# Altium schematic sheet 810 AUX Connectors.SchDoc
size Letter; Organization: Toradex Solutions Inc.; Address1: 6415 Northwest Drive; Address2: Mississauga, ON, L4V 1X1; Address3: Canada
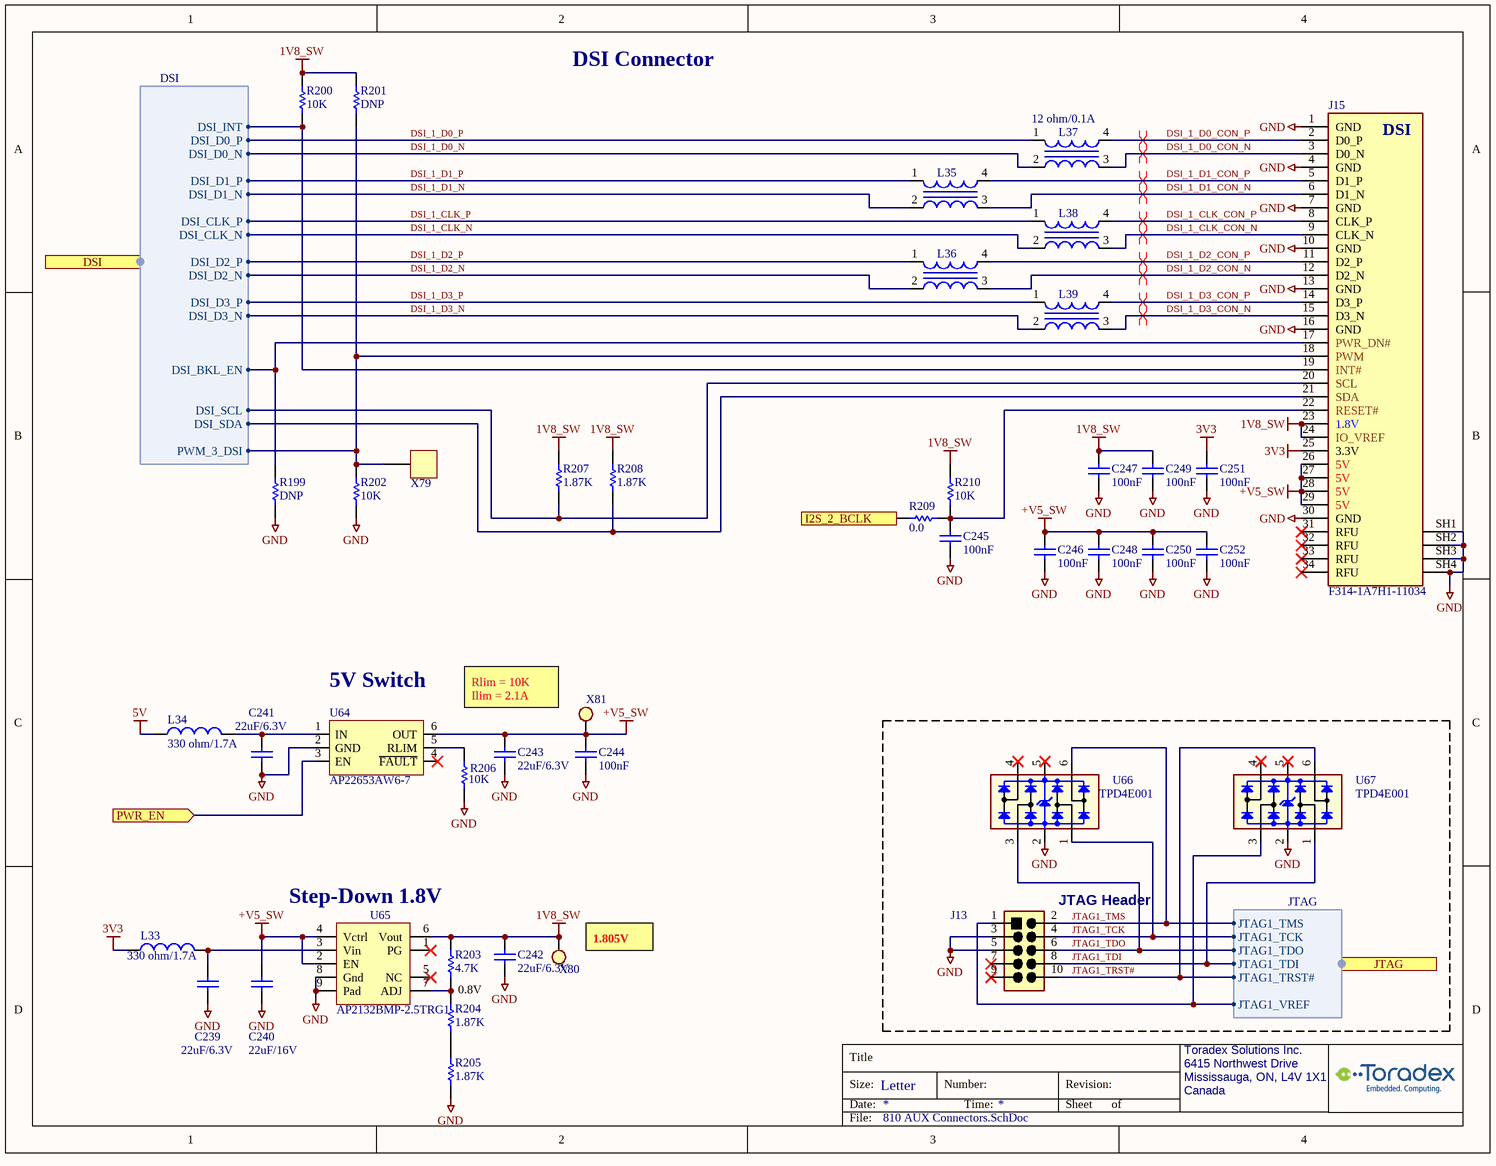
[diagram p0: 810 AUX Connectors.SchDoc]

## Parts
C239  22uF/6.3V  [C0402_CAPC1005L]
C240  value 22uF/16V  [C/0805]  (hidden comment: 1314-Cap-0805-22uF/16V)
C241  22uF/6.3V  [C0402_CAPC1005L]
C242  22uF/6.3V  [C0402_CAPC1005L]
C243  22uF/6.3V  [C0402_CAPC1005L]
C244  100nF  [C0402_CAPC1005L]
C245  100nF  [C0402_CAPC1005L]
C246  100nF  [C0402_CAPC1005L]
C247  100nF  [C0402_CAPC1005L]
C248  100nF  [C0402_CAPC1005L]
C249  100nF  [C0402_CAPC1005L]
C250  100nF  [C0402_CAPC1005L]
C251  100nF  [C0402_CAPC1005L]
C252  100nF  [C0402_CAPC1005L]
J13  FTSH-105-01-L-DV-K  [SAMTEC_FTSH-105-01-L-DV-K-TR]  (value not drawn)
J15  F314-1A7H1-11034  [AMPHENOL_F314-1A7H1-11034]
L33  value 330 ohm/1.7A  [INDC1608x095]  (hidden comment: 0405-Fer-0603-330ohm/1.7A)
L34  value 330 ohm/1.7A  [INDC1608x095]  (hidden comment: 0405-Fer-0603-330ohm/1.7A)
L35  12 ohm/0.1A  [COIL0302]  (value not drawn)
L36  12 ohm/0.1A  [COIL0302]  (value not drawn)
L37  12 ohm/0.1A  [COIL0302]
L38  12 ohm/0.1A  [COIL0302]  (value not drawn)
L39  12 ohm/0.1A  [COIL0302]  (value not drawn)
R199  value DNP  [R0402_RESC1005L]  (hidden comment: 0000-Res-0402-DNP)
R200  value 10K  [R0402_RESC1005L]  (hidden comment: 1572-Res-0402-10K)
R201  value DNP  [R0402_RESC1005L]  (hidden comment: 0000-Res-0402-DNP)
R202  value 10K  [R0402_RESC1005L]  (hidden comment: 1572-Res-0402-10K)
R203  value 4.7K  [R0402_RESC1005L]  (hidden comment: 2233-Res-0402-4.7K)
R204  value 1.87K  [R0402_RESC1005L]  (hidden comment: 1536-Res-0402-1.87K)
R205  value 1.87K  [R0402_RESC1005L]  (hidden comment: 1536-Res-0402-1.87K)
R206  value 10K  [R0402_RESC1005L]  (hidden comment: 1572-Res-0402-10K)
R207  value 1.87K  [R0402_RESC1005L]  (hidden comment: 1536-Res-0402-1.87K)
R208  value 1.87K  [R0402_RESC1005L]  (hidden comment: 1536-Res-0402-1.87K)
R209  value 0.0  [R/0603]  (hidden comment: 0195-Res-0603-0.0ohm)
R210  value 10K  [R0402_RESC1005L]  (hidden comment: 1572-Res-0402-10K)
U64  AP22653AW6-7  [sot23-6]
U65  AP2132BMP-2.5TRG1  [SOP-9 TP_ALT]
U66  TPD4E001  [SOT23-6]
U67  TPD4E001  [SOT23-6]
X79  000-TestPoint  [TestPoint_1]  (value not drawn)
X80  000-TestPoint2  [TestPoint_3]  (value not drawn)
X81  000-TestPoint2  [TestPoint_3]  (value not drawn)

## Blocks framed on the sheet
JTAG Header: J13 U66 U67

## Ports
DSI (harness DSI), I2S_2_BCLK (in), JTAG (harness JTAG), PWR_EN (in)

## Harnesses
JTAG: JTAG1_TDI, JTAG1_TRST#, JTAG1_TDO, JTAG1_VREF, JTAG1_TCK, JTAG1_TMS
DSI: DSI_SDA, DSI_SCL, DSI_BKL_EN, PWM_3_DSI, DSI_INT, DSI_D3_N, DSI_D3_P, DSI_D2_N, DSI_D2_P, DSI_CLK_N, DSI_CLK_P, DSI_D1_N, DSI_D1_P, DSI_D0_N, DSI_D0_P

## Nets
1V8_SW: C242.2 C247.2 C249.2 J15.23(1.8V) J15.24(IO_VREF) R200.2 R201.2 R203.2 R207.2 R208.2 R210.2 U65.6(Vout) X80.1
3V3: C251.2 J15.25(3.3V) L33.1
5V: L34.1
+V5_SW: C240.2 C243.2 C244.2 C246.2 C248.2 C250.2 C252.2 J15.26(5V) J15.27(5V) J15.28(5V) J15.29(5V) U64.6(OUT) U65.2(EN) U65.4(Vctrl) X81.1
GND: C239.1 C240.1 C241.1 C242.1 C243.1 C244.1 C245.1 C246.1 C247.1 C248.1 C249.1 C250.1 C251.1 C252.1 J13.3 J13.5 J15.1(GND) J15.4(GND) J15.7(GND) J15.10(GND) J15.13(GND) J15.16(GND) J15.30(GND) J15.SH1 J15.SH2 J15.SH3 J15.SH4 R199.1 R202.1 R205.1 R206.1 U64.2(GND) U65.8(Gnd) U65.9(Pad) U66.2 U67.2
DSI_1_CLK_CON_N: J15.9(CLK_N) L38.3
DSI_1_CLK_CON_P: J15.8(CLK_P) L38.4
DSI_1_CLK_N: L38.2 ; port DSI.DSI_CLK_N
DSI_1_CLK_P: L38.1 ; port DSI.DSI_CLK_P
DSI_1_D0_CON_N: J15.3(D0_N) L37.3
DSI_1_D0_CON_P: J15.2(D0_P) L37.4
DSI_1_D0_N: L37.2 ; port DSI.DSI_D0_N
DSI_1_D0_P: L37.1 ; port DSI.DSI_D0_P
DSI_1_D1_CON_N: J15.6(D1_N) L35.3
DSI_1_D1_CON_P: J15.5(D1_P) L35.4
DSI_1_D1_N: L35.2 ; port DSI.DSI_D1_N
DSI_1_D1_P: L35.1 ; port DSI.DSI_D1_P
DSI_1_D2_CON_N: J15.12(D2_N) L36.3
DSI_1_D2_CON_P: J15.11(D2_P) L36.4
DSI_1_D2_N: L36.2 ; port DSI.DSI_D2_N
DSI_1_D2_P: L36.1 ; port DSI.DSI_D2_P
DSI_1_D3_CON_N: J15.15(D3_N) L39.3
DSI_1_D3_CON_P: J15.14(D3_P) L39.4
DSI_1_D3_N: L39.2 ; port DSI.DSI_D3_N
DSI_1_D3_P: L39.1 ; port DSI.DSI_D3_P
I2S_2_BCLK: R209.1 ; port I2S_2_BCLK
JTAG1_TCK: J13.4 U66.1 ; port JTAG.JTAG1_TCK
JTAG1_TDI: J13.8 U67.1 ; port JTAG.JTAG1_TDI
JTAG1_TDO: J13.6 U66.3 ; port JTAG.JTAG1_TDO
JTAG1_TMS: J13.2 U66.6 ; port JTAG.JTAG1_TMS
JTAG1_TRST#: J13.10 U67.6 ; port JTAG.JTAG1_TRST#
PWR_EN: U64.3(EN) ; port PWR_EN
NetC239_2: C239.2 L33.2 U65.3(Vin)
NetC241_2: C241.2 L34.2 U64.1(IN)
NetC245_2: C245.2 J15.22(RESET#) R209.2 R210.1
NetJ13_1: J13.1 U67.3 ; port JTAG.JTAG1_VREF
NetJ15_17: J15.17(PWR_DN#) R199.2 ; port DSI.DSI_BKL_EN
NetJ15_18: J15.18(PWM) R201.1 R202.2 X79.1 ; port DSI.PWM_3_DSI
NetJ15_19: J15.19(INT#) R200.1 ; port DSI.DSI_INT
NetJ15_20: J15.20(SCL) R207.1 ; port DSI.DSI_SCL
NetJ15_21: J15.21(SDA) R208.1 ; port DSI.DSI_SDA
NetR203_1: R203.1 R204.2 U65.7(ADJ)
NetR204_1: R204.1 R205.2
NetR206_2: R206.2 U64.5(RLIM)

Not connected (* = marked no-connect by the designer): J13 7* 9*; J15 31(RFU)* 32(RFU)* 33(RFU)* 34(RFU)*; U64 4(~{FAULT})*; U65 1(PG)* 5(NC)*; U66 4* 5*; U67 4* 5*

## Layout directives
differential pair; differential pair class DSI; differential pair class DSI_1_CON: DSI_1_CLK_CON_N, DSI_1_CLK_CON_P, DSI_1_D0_CON_N, DSI_1_D0_CON_P, DSI_1_D1_CON_N, DSI_1_D1_CON_P, DSI_1_D2_CON_N, DSI_1_D2_CON_P, DSI_1_D3_CON_N, DSI_1_D3_CON_P

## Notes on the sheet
- DSI Connector
- (near U64) 5V Switch
- Rlim = 10K
  Ilim = 2.1A
- Step-Down 1.8V
- (near X80) 1.805V
- 0.8V

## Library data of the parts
C239 C241-C243 = 2404-Cap-0402-22uF/6.3V: (-55 to 85 DegC) CAP CER 22UF 6.3V 20% X5R 0402; MfrNo: GRM155R60J226ME11D; Mfr: Murata; PN: 2404
C240 = 1314-Cap-0805-22uF/16V: (-55 to 85 DegC) CAP CER 22uF 16V X5R 0805; MfrNo: CL21A226MOQNNNE; Mfr: Samsung; PN: 1314; Alt: CL21A226MOCLRNC,CL21A226KOQNNNG,GRM21BR61C226ME44L,EMK212BBJ226MG-T
C244-C252 = 1566-Cap-0402-100nF/50V: (-55 to 125 DegC AEC) Cap Ceramic 0.1uF 50V X7R 10% 0402; MfrNo: GRT155R71H104KE01D; Mfr: Murata; Alt: CL05B104KB54PNC,GCM155R71H104ME02D,GCM155R71H104KE02D,GCM155R71H104KE02J; PN: 1566
J13 = 1486-Conn-Header 5X2 SMT Vert: (-55 to 125 DegC) CONN HEADER VERT 10POS 2x5 1.27MM SMT Gold Shroud; MfrNo: FTSH-105-01-L-DV-K-TR; Mfr: Samtec; PN: 1486
J15 = 2373-F314-1A7H1-11034: (-40 to 105 DegC) CONN FFC SIDE 34POS 0.5MM VERT; Mfr: Amphenol ICC / FCI; PN: 2373
L33 L34 = 0405-Fer-0603-330ohm/1.7A: (-55 to 125 DegC) FERRITE BEAD 330 OHM 0603 1.7A 80mohm, typ 48mohm; Mfr: TDK Corporation; MfrNo: MPZ1608S331ATA00; PN: 405; TR: 445-5221-2-ND; DR: 445-5221-6-ND; DR2: 810-MPZ1608S331ATA00
L35-L39 = 1371-Ind-0.8x0.6-12ohm/0.1A-Choke: (-40 to 85 DegC) Ind CMC Choke 12 Ohm 0.1A 1ohm 0.85x0.65x0.5mm; MfrNo: EXC-14CH120U; Mfr: Panasonic; PN: 1371
R199 R201 = 0000-Res-0402-DNP: RES 0402
R200 R202 R206 R210 = 1572-Res-0402-10K: (-55 to 155 DegC AEC) RES 10K OHM 1% 1/16W 100ppm 0402; Mfr: Stackpole Electronics; MfrNo: RMCF0402FT10K0; Alt: AC0402FR-0710KL,AC0402FR-1310KL,CRGCQ0402F10K; PN: 1572
R203 = 2233-Res-0402-4.7K: (-55 to 155 DegC) RES 4.70K OHM 1/16W 1% 0402 100ppm; MfrNo: RC0402FR-074K7L; Mfr: Yageo; PN: 2233
R204 R205 R207 R208 = 1536-Res-0402-1.87K: (-55 to 155 DegC AEC) RES 1.87K OHM 1% 1/16W 100ppm 0402; MfrNo: RMCF0402FT1K87; Mfr: Stackpole Electronics; Alt: AC0402FR-071K87L,RK73H1ETTP1871F,ERJ-2RKF1871X; PN: 1536
R209 = 0195-Res-0603-0.0ohm: RES 0.0 OHM 1/10W JUMP 0603; Mfr: Samsung; MfrNo: RC1608J000CS; Alt: 311-0.0GRCT-ND; Alt2: A106051CT-ND; PN: 195; TR: 1276-3510-2-ND
U64 = 1475-AP22653: (-40 to 85 DegC) IC PWR SWITCH 3-5.5V EN-Active-High ENth:1.5V With-Discharge 65mohm typ ADJ 0.1-2.1A 6SSOP; Mfr: Diodes; PN: 1475; Note: Similar: BD2222G, BD2242G, TPS25221, TPS2553, RT9728A, RT9728B, RT9728C, AP2553, MIC2009YM6, MIC2019YM6, MIC2009A-1YM6,MIC2019A-1YM6
U65 = 1467-AP2132BMP-2.5: (-40 to 85 DegC) IC REG LDO LINEAR POS ADJ 5V 2A 8SO; Mfr: Diodes; PN: 1467; Desc: (-40 to 85 DegC) IC REG BUCK ADJ Sync 5A Vin:3.8 to 40V 100-2200kHz FSS (spread spectrum) MaxDuty:100% SO-8EP; Note: These can be also used with adjust Voltage circuit: AP2132BMP-1.2TRG1, AP2132BMP-1.5TRG1
U66 U67 = 0740-TPD4E001: (-40 to 125 DegC AEC) TVS DIODE 5.5VWM 16VC SOT-23-6; MfrNo: TPD4E001QDBVRQ1; Mfr: Texas Instruments; PN: 740; Alt: TPD4E001DBVR
X79 = 000-TestPoint: Note: this is PCB footprint only, no parts to buy or assemble
X80 X81 = 000-TestPoint2: TestPoint SMD; Note: PCB footprint only, no parts to buy or assemble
